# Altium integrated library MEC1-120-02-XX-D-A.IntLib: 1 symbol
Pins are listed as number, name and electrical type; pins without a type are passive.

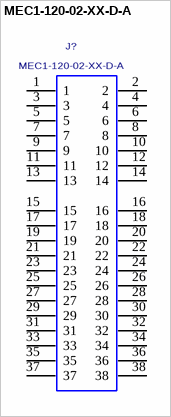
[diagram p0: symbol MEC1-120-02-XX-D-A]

## MEC1-120-02-XX-D-A
designator J?
1MM MIN-EDGE CARD ASSEMBLY; MANUFACTURER: SAMTEC
footprint MEC1-120-02-XX-D-A
pins: 1, 2, 3, 4, 5, 6, 7, 8, 9, 10, 11, 12, 13, 14, 15, 16, 17, 18, 19, 20, 21, 22, 23, 24, 25, 26, 27, 28, 29, 30, 31, 32, 33, 34, 35, 36, 37, 38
